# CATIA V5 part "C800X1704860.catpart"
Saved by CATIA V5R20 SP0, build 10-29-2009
Part number: C800X1704860
Source: Unknown
Property "A": "70"
Property "ARTICLENO": "C800X1704860"
Property "B": "32"
Property "BOMINFO": "C800X1704860"
Property "C": "120"
Property "CA": "C800X1704860"
Property "D1": "120"
Property "DES": "ROTATING EYEBOLT WITH RING Ton 17,0 M48x60"
Property "E": "112"
Property "H": "262"
Property "L": "60"
Property "LINA": "C800X1704860"
Property "NB": "C800X1704860"
Property "NBSYN": "$CODE."
Property "NN": "C800X"
Property "NT": "Rotating eyebolt with ring"
Property "SIZE": "M48"
Property "SUPPLIER": "CF"
Property "SW": "100"
Property "WEIGHT": "10900"
Property "WLL": "17.00"
Bounding box of the stored display mesh (mm): x -67 to 67, y -60 to 293.813, z -60 to 60
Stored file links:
  C:\Users\Utente\Desktop\3D files 800X\C800X1704860.catpart
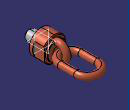
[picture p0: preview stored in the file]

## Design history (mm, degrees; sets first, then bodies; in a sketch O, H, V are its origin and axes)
Body1 "Geometry.1" (main body)
  Solid1 "C800X1704860.catpart": solid without history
